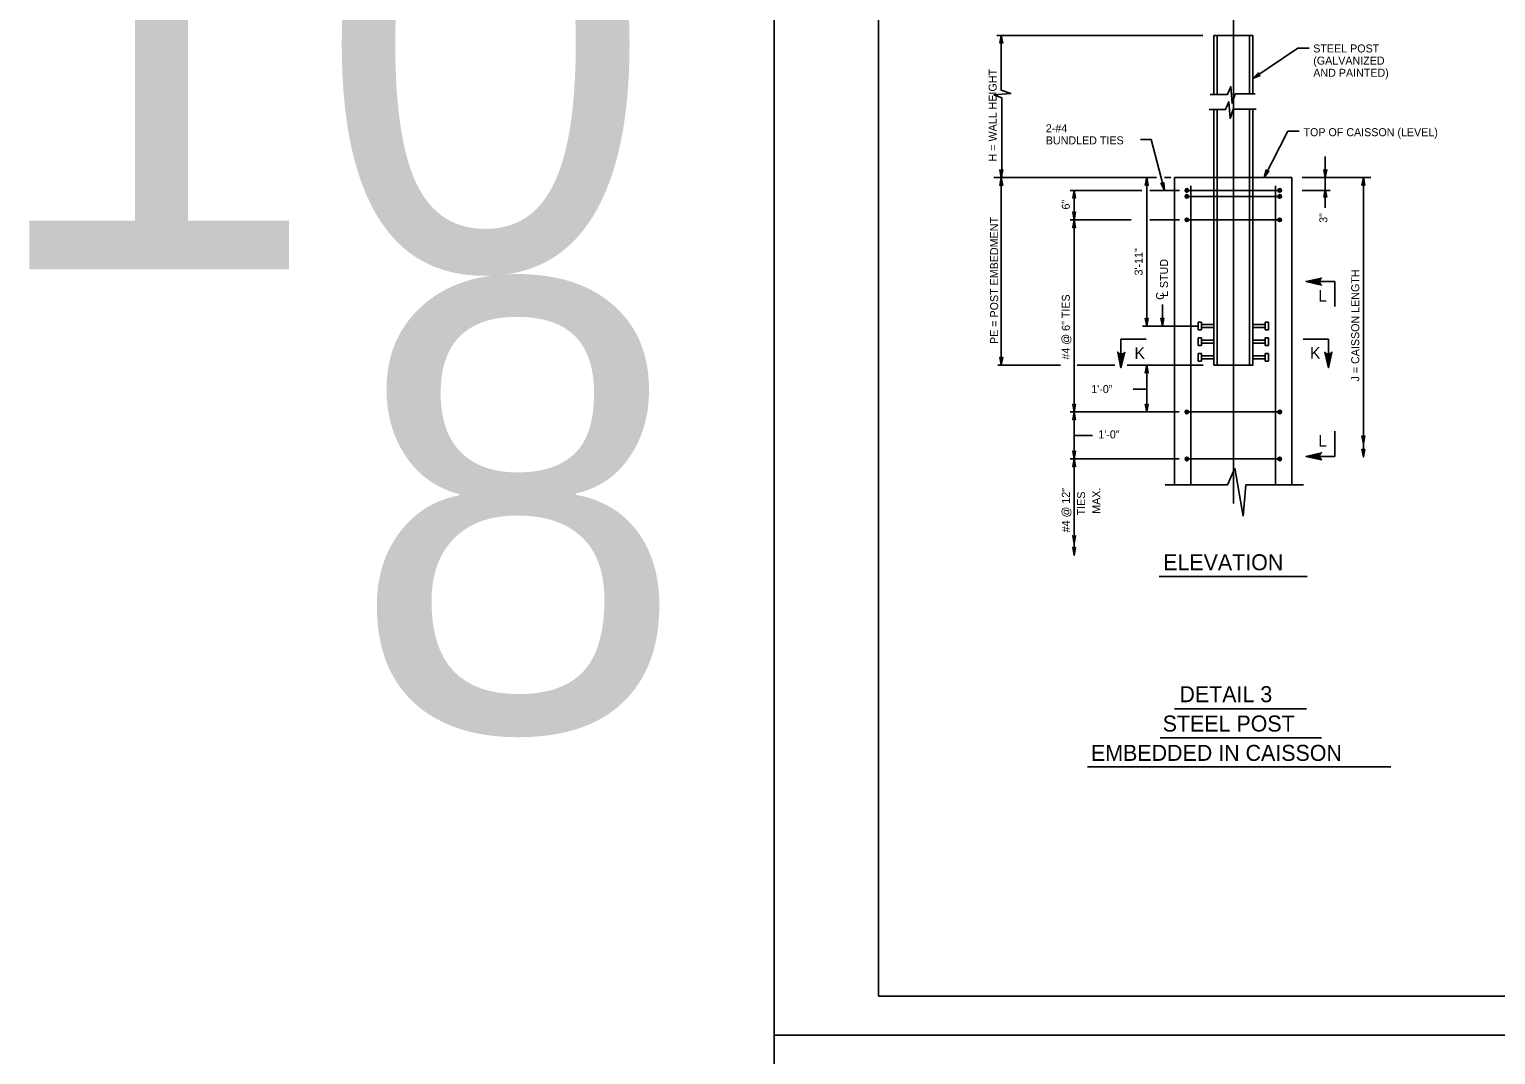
# Model space of a CAD drawing. Extents: x 3475 to 6558, y -3780 to 1166.
# Drawn here: x 3475 to 4038, y -1812 to -1418 of the extents above; entities that cross this region are included whole.
import ezdxf

# ---------------------------------------------------------------- set-up
doc = ezdxf.new("R2010")
doc.units = 0
for name, color, linetype in [('1', 7, 'Continuous'), ('2', 7, 'Continuous'), ('PLT-BNDY', 7, 'Continuous')]:
    doc.layers.add(name, color=color, linetype=linetype)

msp = doc.modelspace()

# ---------------------------------------------------------------- linework, layer by layer
at = {"layer": '1'}
for p, q in [((3937.55, -1403.75), (3937.55, -1600.18)), ((3846.7, -1420.47), (3925.79, -1420.47)), ((3930.05, -1420.47), (3945.05, -1420.47)), ((3930.05, -1420.47), (3930.05, -1442.99)), ((3931.31, -1420.47), (3931.31, -1442.99)), ((3943.79, -1420.47), (3943.79, -1442.99)), ((3945.05, -1420.47), (3945.05, -1442.99)), ((3930.05, -1448.91), (3930.05, -1547.05)), ((3931.31, -1448.91), (3931.31, -1547.05)), ((3943.79, -1448.75), (3943.79, -1547.05)), ((3945.05, -1448.75), (3945.05, -1547.05)), ((3905.95, -1460.44), (3901.87, -1460.44)), ((3911.07, -1479.98), (3905.95, -1460.44)), ((3972.85, -1486.71), (3972.85, -1467.01)), ((3908.05, -1475.05), (3845.65, -1475.05)), ((3848.47, -1547.05), (3848.47, -1475.06)), ((3902.38, -1479.98), (3874.9, -1479.98)), ((3876.45, -1479.98), (3876.45, -1491.28)), ((3904.32, -1532.05), (3904.32, -1475.05)), ((3916.93, -1479.98), (3905.55, -1479.98)), ((3913.51, -1475.05), (3911.1, -1475.05)), ((3919.69, -1479.98), (3955.35, -1479.98)), ((3921.25, -1478.17), (3921.25, -1592.98)), ((3953.74, -1478.17), (3953.74, -1592.98)), ((3963.95, -1475.05), (3990.26, -1475.05)), ((3963.95, -1479.98), (3974.7, -1479.98)), ((3987.45, -1475.04), (3987.45, -1582.33)), ((3919.69, -1482.28), (3955.35, -1482.28)), ((3898.33, -1491.28), (3874.9, -1491.28)), ((3876.45, -1491.28), (3876.45, -1565.05)), ((3916.93, -1491.28), (3905.55, -1491.28)), ((3919.69, -1491.28), (3955.35, -1491.28)), ((3965.45, -1514.93), (3976.45, -1514.93)), ((3976.45, -1524.58), (3976.45, -1514.93)), ((3910.3, -1532.05), (3910.3, -1523.82)), ((3924.05, -1530.61), (3924.05, -1533.49)), ((3924.05, -1530.61), (3925.31, -1530.61)), ((3925.31, -1530.61), (3925.31, -1533.49)), ((3949.79, -1530.61), (3949.79, -1533.49)), ((3949.79, -1530.61), (3951.05, -1530.61)), ((3951.05, -1530.61), (3951.05, -1533.49)), ((3924.05, -1532.05), (3902.73, -1532.05)), ((3924.05, -1533.49), (3925.31, -1533.49)), ((3924.05, -1536.61), (3924.05, -1539.49)), ((3924.05, -1536.61), (3925.31, -1536.61)), ((3925.31, -1531.51), (3930.05, -1531.51)), ((3925.31, -1532.59), (3930.05, -1532.59)), ((3925.31, -1536.61), (3925.31, -1539.49)), ((3945.05, -1531.51), (3949.79, -1531.51)), ((3945.05, -1532.59), (3949.79, -1532.59)), ((3949.79, -1533.49), (3951.05, -1533.49)), ((3949.79, -1536.61), (3949.79, -1539.49)), ((3949.79, -1536.61), (3951.05, -1536.61)), ((3951.05, -1536.61), (3951.05, -1539.49)), ((3904.07, -1537.05), (3894.42, -1537.05)), ((3894.42, -1548.05), (3894.42, -1537.05)), ((3924.05, -1539.49), (3925.31, -1539.49)), ((3925.31, -1537.51), (3930.05, -1537.51)), ((3925.31, -1538.59), (3930.05, -1538.59)), ((3945.05, -1537.51), (3949.79, -1537.51)), ((3945.05, -1538.59), (3949.79, -1538.59)), ((3949.79, -1539.49), (3951.05, -1539.49)), ((3964.4, -1537.05), (3974.05, -1537.05)), ((3974.05, -1548.05), (3974.05, -1537.05)), ((3871.22, -1547.05), (3847.09, -1547.05)), ((3892.04, -1547.05), (3877.62, -1547.05)), ((3925.92, -1547.05), (3896.76, -1547.05)), ((3904.32, -1547.05), (3904.32, -1565.05)), ((3924.05, -1542.61), (3924.05, -1545.49)), ((3924.05, -1542.61), (3925.31, -1542.61)), ((3924.05, -1545.49), (3925.31, -1545.49)), ((3925.31, -1542.61), (3925.31, -1545.49)), ((3925.31, -1543.51), (3930.05, -1543.51)), ((3925.31, -1544.59), (3930.05, -1544.59)), ((3930.05, -1547.05), (3945.05, -1547.05)), ((3945.05, -1543.51), (3949.79, -1543.51)), ((3945.05, -1544.59), (3949.79, -1544.59)), ((3949.79, -1542.61), (3949.79, -1545.49)), ((3949.79, -1542.61), (3951.05, -1542.61)), ((3949.79, -1545.49), (3951.05, -1545.49)), ((3951.05, -1542.61), (3951.05, -1545.49)), ((3904.32, -1556.35), (3899.11, -1556.35)), ((3916.69, -1565.05), (3874.9, -1565.05)), ((3876.45, -1565.05), (3876.45, -1583.05)), ((3919.69, -1565.05), (3955.35, -1565.05)), ((3883.45, -1574.11), (3876.45, -1574.11)), ((3976.45, -1572.45), (3976.45, -1582.1)), ((3916.69, -1583.05), (3874.9, -1583.05)), ((3876.45, -1583.05), (3876.45, -1620.06)), ((3919.69, -1583.05), (3955.35, -1583.05)), ((3935.24, -1592.98), (3938.09, -1586.57)), ((3938.09, -1586.57), (3941.29, -1605.08)), ((3965.45, -1582.1), (3976.45, -1582.1)), ((3911.4, -1592.98), (3935.24, -1592.98)), ((3941.29, -1605.08), (3942.36, -1592.98)), ((3942.36, -1592.98), (3964.54, -1592.98)), ((3909.03, -1628.26), (3965.91, -1628.26)), ((3915, -1679.01), (3965.67, -1679.01)), ((3909.5, -1690.1), (3971.41, -1690.1)), ((3881.54, -1701.31), (3997.94, -1701.31))]:
    msp.add_line(p, q, dxfattribs=at)
for points in [[(3848.62, -1475.05), (3848.62, -1444.5), (3845.65, -1443.25), (3852.07, -1442.78), (3848.47, -1441.53), (3848.47, -1420.47)], [(3848.47, -1420.47), (3849.03, -1423.45), (3848.87, -1423.22), (3848.67, -1423.1), (3848.47, -1423.07), (3848.27, -1423.1), (3848.07, -1423.22), (3847.91, -1423.45), (3848.47, -1420.47), (3848.07, -1423.22), (3848.27, -1423.1), (3848.47, -1420.47), (3848.47, -1423.07), (3848.67, -1423.1), (3848.47, -1420.47), (3848.87, -1423.22)], [(3966.6, -1425.37), (3962.34, -1425.37), (3945.05, -1437.01)], [(3945.05, -1437.01), (3947.21, -1434.88), (3947.11, -1435.14), (3947.12, -1435.38), (3947.21, -1435.56), (3947.35, -1435.71), (3947.56, -1435.81), (3947.84, -1435.81), (3945.05, -1437.01), (3947.56, -1435.81), (3947.35, -1435.71), (3945.05, -1437.01), (3947.21, -1435.56), (3947.12, -1435.38), (3945.05, -1437.01), (3947.11, -1435.14)], [(3928.61, -1443.12), (3935.33, -1443.12), (3936.58, -1440.14), (3937.05, -1446.56), (3938.3, -1442.96), (3945.97, -1442.96)], [(3928.3, -1448.91), (3934.55, -1448.91), (3935.8, -1445.93), (3936.27, -1452.35), (3937.52, -1448.75), (3946.28, -1448.75)], [(3962.77, -1457.25), (3958.5, -1457.25), (3949.34, -1475.05)], [(3848.47, -1475.06), (3847.91, -1472.08), (3848.07, -1472.31), (3848.27, -1472.43), (3848.47, -1472.46), (3848.67, -1472.43), (3848.87, -1472.31), (3849.03, -1472.08), (3848.47, -1475.06), (3848.87, -1472.31), (3848.67, -1472.43), (3848.47, -1475.06), (3848.47, -1472.46), (3848.27, -1472.43), (3848.47, -1475.06), (3848.07, -1472.31)], [(3949.34, -1475.05), (3950.2, -1472.14), (3950.24, -1472.42), (3950.36, -1472.61), (3950.53, -1472.74), (3950.72, -1472.8), (3950.95, -1472.78), (3951.2, -1472.65), (3949.34, -1475.05), (3950.95, -1472.78), (3950.72, -1472.8), (3949.34, -1475.05), (3950.53, -1472.74), (3950.36, -1472.61), (3949.34, -1475.05), (3950.24, -1472.42)], [(3972.85, -1475.05), (3972.29, -1472.07), (3972.45, -1472.3), (3972.65, -1472.41), (3972.85, -1472.45), (3973.05, -1472.41), (3973.25, -1472.3), (3973.41, -1472.07), (3972.85, -1475.05), (3973.25, -1472.3), (3973.05, -1472.41), (3972.85, -1475.05), (3972.85, -1472.45), (3972.65, -1472.41), (3972.85, -1475.05), (3972.45, -1472.3)], [(3848.47, -1475.06), (3849.03, -1478.05), (3848.87, -1477.82), (3848.67, -1477.7), (3848.47, -1477.66), (3848.27, -1477.7), (3848.07, -1477.82), (3847.91, -1478.05), (3848.47, -1475.06), (3848.07, -1477.82), (3848.27, -1477.7), (3848.47, -1475.06), (3848.47, -1477.66), (3848.67, -1477.7), (3848.47, -1475.06), (3848.87, -1477.82)], [(3876.45, -1479.98), (3877.01, -1482.96), (3876.85, -1482.73), (3876.65, -1482.61), (3876.45, -1482.58), (3876.25, -1482.61), (3876.05, -1482.73), (3875.89, -1482.96), (3876.45, -1479.98), (3876.05, -1482.73), (3876.25, -1482.61), (3876.45, -1479.98), (3876.45, -1482.58), (3876.65, -1482.61), (3876.45, -1479.98), (3876.85, -1482.73)], [(3904.32, -1475.05), (3904.88, -1478.03), (3904.72, -1477.8), (3904.52, -1477.68), (3904.32, -1477.65), (3904.12, -1477.68), (3903.92, -1477.8), (3903.76, -1478.03), (3904.32, -1475.05), (3903.92, -1477.8), (3904.12, -1477.68), (3904.32, -1475.05), (3904.32, -1477.65), (3904.52, -1477.68), (3904.32, -1475.05), (3904.72, -1477.8)], [(3911.07, -1479.98), (3909.77, -1477.24), (3909.99, -1477.42), (3910.21, -1477.48), (3910.41, -1477.47), (3910.6, -1477.38), (3910.76, -1477.22), (3910.85, -1476.95), (3911.07, -1479.98), (3910.76, -1477.22), (3910.6, -1477.38), (3911.07, -1479.98), (3910.41, -1477.47), (3910.21, -1477.48), (3911.07, -1479.98), (3909.99, -1477.42)], [(3959.97, -1592.62), (3959.97, -1475.05), (3914.97, -1475.05), (3914.97, -1592.62)], [(3972.85, -1479.55), (3973.41, -1482.53), (3973.25, -1482.3), (3973.05, -1482.18), (3972.85, -1482.15), (3972.65, -1482.18), (3972.45, -1482.3), (3972.29, -1482.53), (3972.85, -1479.55), (3972.45, -1482.3), (3972.65, -1482.18), (3972.85, -1479.55), (3972.85, -1482.15), (3973.05, -1482.18), (3972.85, -1479.55), (3973.25, -1482.3)], [(3987.45, -1475.04), (3988.01, -1478.03), (3987.85, -1477.8), (3987.65, -1477.68), (3987.45, -1477.64), (3987.25, -1477.68), (3987.05, -1477.8), (3986.89, -1478.03), (3987.45, -1475.04), (3987.05, -1477.8), (3987.25, -1477.68), (3987.45, -1475.04), (3987.45, -1477.64), (3987.65, -1477.68), (3987.45, -1475.04), (3987.85, -1477.8)], [(3876.45, -1491.28), (3875.89, -1488.3), (3876.05, -1488.53), (3876.25, -1488.65), (3876.45, -1488.68), (3876.65, -1488.65), (3876.85, -1488.53), (3877.01, -1488.3), (3876.45, -1491.28), (3876.85, -1488.53), (3876.65, -1488.65), (3876.45, -1491.28), (3876.45, -1488.68), (3876.25, -1488.65), (3876.45, -1491.28), (3876.05, -1488.53)], [(3876.45, -1491.28), (3877.01, -1494.27), (3876.85, -1494.04), (3876.65, -1493.92), (3876.45, -1493.88), (3876.25, -1493.92), (3876.05, -1494.04), (3875.89, -1494.27), (3876.45, -1491.28), (3876.05, -1494.04), (3876.25, -1493.92), (3876.45, -1491.28), (3876.45, -1493.88), (3876.65, -1493.92), (3876.45, -1491.28), (3876.85, -1494.04)], [(3965.45, -1514.93), (3971.41, -1516.35), (3971.18, -1516.15), (3970.95, -1515.96), (3970.83, -1515.72), (3970.72, -1515.47), (3970.68, -1515.23), (3970.65, -1514.99), (3970.69, -1514.75), (3970.72, -1514.51), (3970.85, -1514.28), (3970.97, -1514.04), (3971.2, -1513.85), (3971.43, -1513.66), (3965.45, -1514.93), (3971.2, -1513.85), (3970.97, -1514.04), (3965.45, -1514.93), (3970.85, -1514.28), (3970.72, -1514.51), (3965.45, -1514.93), (3970.69, -1514.75), (3970.65, -1514.99), (3965.45, -1514.93), (3970.68, -1515.23), (3970.72, -1515.47), (3965.45, -1514.93), (3970.83, -1515.72), (3970.95, -1515.96), (3965.45, -1514.93), (3971.18, -1516.15)], [(3904.32, -1532.05), (3903.76, -1529.06), (3903.92, -1529.29), (3904.12, -1529.41), (3904.32, -1529.45), (3904.52, -1529.41), (3904.72, -1529.29), (3904.88, -1529.06), (3904.32, -1532.05), (3904.72, -1529.29), (3904.52, -1529.41), (3904.32, -1532.05), (3904.32, -1529.45), (3904.12, -1529.41), (3904.32, -1532.05), (3903.92, -1529.29)], [(3910.3, -1532.05), (3909.74, -1529.06), (3909.9, -1529.29), (3910.1, -1529.41), (3910.3, -1529.45), (3910.5, -1529.41), (3910.7, -1529.29), (3910.86, -1529.06), (3910.3, -1532.05), (3910.7, -1529.29), (3910.5, -1529.41), (3910.3, -1532.05), (3910.3, -1529.45), (3910.1, -1529.41), (3910.3, -1532.05), (3909.9, -1529.29)], [(3894.42, -1548.05), (3895.83, -1542.1), (3895.64, -1542.33), (3895.45, -1542.56), (3895.21, -1542.67), (3894.96, -1542.79), (3894.72, -1542.82), (3894.48, -1542.85), (3894.24, -1542.82), (3894, -1542.78), (3893.77, -1542.66), (3893.53, -1542.54), (3893.34, -1542.31), (3893.15, -1542.08), (3894.42, -1548.05), (3893.34, -1542.31), (3893.53, -1542.54), (3894.42, -1548.05), (3893.77, -1542.66), (3894, -1542.78), (3894.42, -1548.05), (3894.24, -1542.82), (3894.48, -1542.85), (3894.42, -1548.05), (3894.72, -1542.82), (3894.96, -1542.79), (3894.42, -1548.05), (3895.21, -1542.67), (3895.45, -1542.56), (3894.42, -1548.05), (3895.64, -1542.33)], [(3974.05, -1548.05), (3972.63, -1542.1), (3972.83, -1542.33), (3973.02, -1542.56), (3973.26, -1542.67), (3973.5, -1542.79), (3973.74, -1542.82), (3973.98, -1542.85), (3974.22, -1542.82), (3974.46, -1542.78), (3974.7, -1542.66), (3974.94, -1542.54), (3975.13, -1542.31), (3975.32, -1542.08), (3974.05, -1548.05), (3975.13, -1542.31), (3974.94, -1542.54), (3974.05, -1548.05), (3974.7, -1542.66), (3974.46, -1542.78), (3974.05, -1548.05), (3974.22, -1542.82), (3973.98, -1542.85), (3974.05, -1548.05), (3973.74, -1542.82), (3973.5, -1542.79), (3974.05, -1548.05), (3973.26, -1542.67), (3973.02, -1542.56), (3974.05, -1548.05), (3972.83, -1542.33)], [(3848.47, -1547.05), (3847.91, -1544.07), (3848.07, -1544.3), (3848.27, -1544.42), (3848.47, -1544.45), (3848.67, -1544.42), (3848.87, -1544.3), (3849.03, -1544.07), (3848.47, -1547.05), (3848.87, -1544.3), (3848.67, -1544.42), (3848.47, -1547.05), (3848.47, -1544.45), (3848.27, -1544.42), (3848.47, -1547.05), (3848.07, -1544.3)], [(3904.32, -1547.05), (3904.88, -1550.03), (3904.72, -1549.8), (3904.52, -1549.68), (3904.32, -1549.65), (3904.12, -1549.68), (3903.92, -1549.8), (3903.76, -1550.03), (3904.32, -1547.05), (3903.92, -1549.8), (3904.12, -1549.68), (3904.32, -1547.05), (3904.32, -1549.65), (3904.52, -1549.68), (3904.32, -1547.05), (3904.72, -1549.8)], [(3876.45, -1565.05), (3875.89, -1562.07), (3876.05, -1562.3), (3876.25, -1562.42), (3876.45, -1562.45), (3876.65, -1562.42), (3876.85, -1562.3), (3877.01, -1562.07), (3876.45, -1565.05), (3876.85, -1562.3), (3876.65, -1562.42), (3876.45, -1565.05), (3876.45, -1562.45), (3876.25, -1562.42), (3876.45, -1565.05), (3876.05, -1562.3)], [(3904.32, -1565.05), (3903.76, -1562.07), (3903.92, -1562.3), (3904.12, -1562.42), (3904.32, -1562.45), (3904.52, -1562.42), (3904.72, -1562.3), (3904.88, -1562.07), (3904.32, -1565.05), (3904.72, -1562.3), (3904.52, -1562.42), (3904.32, -1565.05), (3904.32, -1562.45), (3904.12, -1562.42), (3904.32, -1565.05), (3903.92, -1562.3)], [(3876.45, -1565.05), (3877.01, -1568.03), (3876.85, -1567.8), (3876.65, -1567.68), (3876.45, -1567.65), (3876.25, -1567.68), (3876.05, -1567.8), (3875.89, -1568.03), (3876.45, -1565.05), (3876.05, -1567.8), (3876.25, -1567.68), (3876.45, -1565.05), (3876.45, -1567.65), (3876.65, -1567.68), (3876.45, -1565.05), (3876.85, -1567.8)], [(3987.45, -1577.25), (3986.89, -1574.26), (3987.05, -1574.49), (3987.25, -1574.61), (3987.45, -1574.65), (3987.65, -1574.61), (3987.85, -1574.49), (3988.01, -1574.26), (3987.45, -1577.25), (3987.85, -1574.49), (3987.65, -1574.61), (3987.45, -1577.25), (3987.45, -1574.65), (3987.25, -1574.61), (3987.45, -1577.25), (3987.05, -1574.49)], [(3876.45, -1583.05), (3875.89, -1580.07), (3876.05, -1580.3), (3876.25, -1580.42), (3876.45, -1580.45), (3876.65, -1580.42), (3876.85, -1580.3), (3877.01, -1580.07), (3876.45, -1583.05), (3876.85, -1580.3), (3876.65, -1580.42), (3876.45, -1583.05), (3876.45, -1580.45), (3876.25, -1580.42), (3876.45, -1583.05), (3876.05, -1580.3)], [(3965.45, -1582.1), (3971.41, -1580.68), (3971.18, -1580.88), (3970.95, -1581.07), (3970.83, -1581.31), (3970.72, -1581.55), (3970.68, -1581.79), (3970.65, -1582.03), (3970.69, -1582.27), (3970.72, -1582.51), (3970.85, -1582.75), (3970.97, -1582.99), (3971.2, -1583.18), (3971.43, -1583.37), (3965.45, -1582.1), (3971.2, -1583.18), (3970.97, -1582.99), (3965.45, -1582.1), (3970.85, -1582.75), (3970.72, -1582.51), (3965.45, -1582.1), (3970.69, -1582.27), (3970.65, -1582.03), (3965.45, -1582.1), (3970.68, -1581.79), (3970.72, -1581.55), (3965.45, -1582.1), (3970.83, -1581.31), (3970.95, -1581.07), (3965.45, -1582.1), (3971.18, -1580.88)], [(3987.45, -1582.33), (3986.89, -1579.35), (3987.05, -1579.58), (3987.25, -1579.7), (3987.45, -1579.73), (3987.65, -1579.7), (3987.85, -1579.58), (3988.01, -1579.35), (3987.45, -1582.33), (3987.85, -1579.58), (3987.65, -1579.7), (3987.45, -1582.33), (3987.45, -1579.73), (3987.25, -1579.7), (3987.45, -1582.33), (3987.05, -1579.58)], [(3876.45, -1583.05), (3877.01, -1586.03), (3876.85, -1585.8), (3876.65, -1585.68), (3876.45, -1585.65), (3876.25, -1585.68), (3876.05, -1585.8), (3875.89, -1586.03), (3876.45, -1583.05), (3876.05, -1585.8), (3876.25, -1585.68), (3876.45, -1583.05), (3876.45, -1585.65), (3876.65, -1585.68), (3876.45, -1583.05), (3876.85, -1585.8)], [(3876.45, -1615.59), (3875.89, -1612.6), (3876.05, -1612.83), (3876.25, -1612.95), (3876.45, -1612.99), (3876.65, -1612.95), (3876.85, -1612.83), (3877.01, -1612.6), (3876.45, -1615.59), (3876.85, -1612.83), (3876.65, -1612.95), (3876.45, -1615.59), (3876.45, -1612.99), (3876.25, -1612.95), (3876.45, -1615.59), (3876.05, -1612.83)], [(3876.45, -1620.06), (3875.89, -1617.08), (3876.05, -1617.31), (3876.25, -1617.43), (3876.45, -1617.46), (3876.65, -1617.43), (3876.85, -1617.31), (3877.01, -1617.08), (3876.45, -1620.06), (3876.85, -1617.31), (3876.65, -1617.43), (3876.45, -1620.06), (3876.45, -1617.46), (3876.25, -1617.43), (3876.45, -1620.06), (3876.05, -1617.31)]]:
    msp.add_lwpolyline(points, dxfattribs=at)
for centre, radius in [((3919.69, -1479.98), 0.701), ((3919.69, -1479.98), 0.53), ((3919.69, -1479.98), 0.379), ((3919.69, -1479.98), 0.215), ((3955.35, -1479.98), 0.701), ((3955.35, -1479.98), 0.53), ((3955.35, -1479.98), 0.379), ((3955.35, -1479.98), 0.215), ((3919.69, -1482.28), 0.701), ((3919.69, -1482.28), 0.53), ((3919.69, -1482.28), 0.379), ((3919.69, -1482.28), 0.215), ((3955.35, -1482.28), 0.701), ((3955.35, -1482.28), 0.53), ((3955.35, -1482.28), 0.379), ((3955.35, -1482.28), 0.215), ((3919.69, -1491.28), 0.701), ((3919.69, -1491.28), 0.53), ((3919.69, -1491.28), 0.379), ((3919.69, -1491.28), 0.215), ((3955.35, -1491.28), 0.701), ((3955.35, -1491.28), 0.53), ((3955.35, -1491.28), 0.379), ((3955.35, -1491.28), 0.215), ((3919.69, -1565.05), 0.701), ((3919.69, -1565.05), 0.53), ((3919.69, -1565.05), 0.379), ((3955.35, -1565.05), 0.701), ((3955.35, -1565.05), 0.53), ((3955.35, -1565.05), 0.379), ((3919.69, -1565.05), 0.215), ((3955.35, -1565.05), 0.215), ((3919.69, -1583.05), 0.701), ((3919.69, -1583.05), 0.53), ((3919.69, -1583.05), 0.379), ((3919.69, -1583.05), 0.215), ((3955.35, -1583.05), 0.701), ((3955.35, -1583.05), 0.53), ((3955.35, -1583.05), 0.379), ((3955.35, -1583.05), 0.215)]:
    msp.add_circle(centre, radius, dxfattribs=at)
at = {"layer": '2'}
for p, q in [((3801.34, -1789.31), (3801.34, -1225.31)), ((4587.34, -1789.31), (3801.34, -1789.31))]:
    msp.add_line(p, q, dxfattribs=at)
at = {"layer": 'PLT-BNDY'}
for points in [[(3761.34, -1210.31), (4602.34, -1210.31), (4602.34, -1804.31), (3761.34, -1804.31)], [(3761.34, -1804.31), (4602.34, -1804.31), (4602.34, -2398.31), (3761.34, -2398.31)]]:
    msp.add_lwpolyline(points, close=True, dxfattribs=at)

# ---------------------------------------------------------------- texts
at = {"layer": '1'}
for s, height, p in [('10', 172.802, (3457.76, -1510.33)), ('STEEL POST', 3.072, (3968.22, -1427.02)), ('(GALVANIZED', 3.072, (3968.22, -1431.69)), ('AND PAINTED)', 3.072, (3968.22, -1436.36)), ('2-#4', 3.072, (3865.55, -1457.67)), ('TOP OF CAISSON (LEVEL)', 3.072, (3964.47, -1459.17)), ('BUNDLED TIES', 3.072, (3865.55, -1462.31)), ('8', 172.8, (3598.73, -1687.47)), ('L', 4.48, (3970.16, -1522.73)), ('K', 4.48, (3899.61, -1544.66)), ('K', 4.48, (3966.97, -1544.63)), ('1\'-0"', 3.072, (3883.01, -1557.81)), ('1\'-0"', 3.072, (3885.72, -1575.19)), ('L', 4.48, (3970.16, -1578.4)), ('ELEVATION', 6.144, (3910.6, -1625.82)), ('DETAIL 3', 6.144, (3916.85, -1676.47)), ('STEEL POST', 6.144, (3910.42, -1687.74)), ('EMBEDDED IN CAISSON', 6.144, (3882.89, -1699))]:
    msp.add_text(s, height=height, dxfattribs=at).set_placement(p)
for s, height, p in [('H = WALL HEIGHT', 3.072, (3846.69, -1468.86)), ('6"', 3.072, (3874.77, -1487.31)), ('PE = POST EMBEDMENT', 3.072, (3847.26, -1538.94)), ('3"', 3.072, (3973.63, -1492.43)), ('3\'-11"', 3.072, (3902.71, -1512.63)), ('L STUD', 3.072, (3912.45, -1520.92)), ('J = CAISSON LENGTH', 3.072, (3985.87, -1553.35)), ('C', 3.07, (3910.97, -1521.98)), ('#4 @ 6" TIES', 3.072, (3874.77, -1544.94)), ('#4 @ 12"', 3.072, (3874.79, -1611.28)), ('TIES', 3.072, (3880.63, -1604.75)), ('MAX.', 3.072, (3886.47, -1604.12))]:
    msp.add_text(s, height=height, rotation=90, dxfattribs=at).set_placement(p)

doc.saveas('drawing.dxf')
